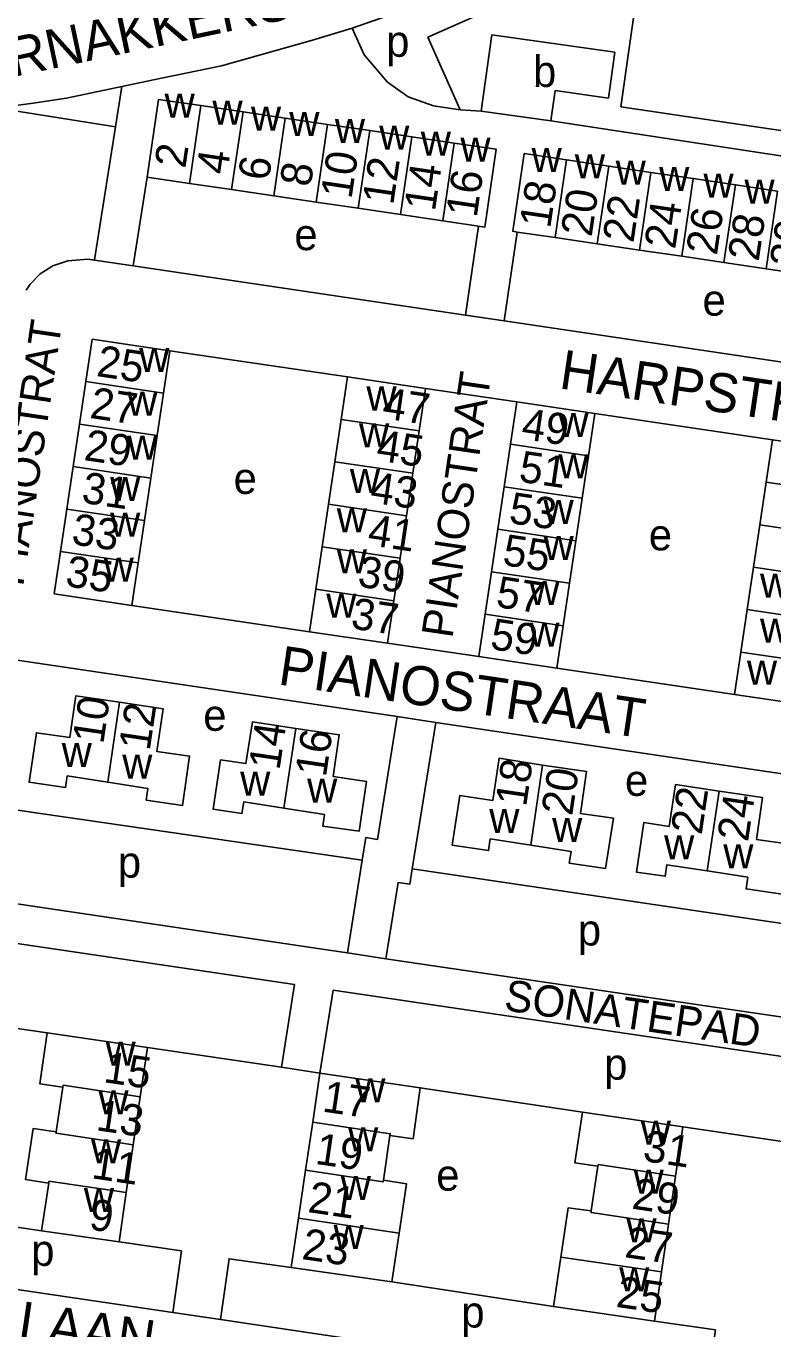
# Model space of a CAD drawing. Extents: x 163012 to 165277, y 382513 to 383987.
# Drawn here: x 164369.8 to 164465.3, y 383209.4 to 383376 of the extents above; entities that cross this region are included whole.
import ezdxf

# ---------------------------------------------------------------- set-up
doc = ezdxf.new("R2010")
doc.units = 0
for name, color, linetype in [('BLT_Basislijn', 7, 'Continuous'), ('BLT_Bebouwing', 7, 'Continuous'), ('BLT_Centroide', 7, 'Continuous'), ('BLT_Huisnummer', 7, 'Continuous'), ('BLT_Huisnummer_ tussenligend', 7, 'Continuous'), ('BLT_Onderverdeling_panden', 7, 'Continuous'), ('BLT_Straatnaam', 7, 'Continuous'), ('BLT_Straatnaam_verkleind', 7, 'Continuous')]:
    doc.layers.add(name, color=color, linetype=linetype)

msp = doc.modelspace()

# ---------------------------------------------------------------- linework, layer by layer
at = {"layer": 'BLT_Basislijn'}
for p, q in [((164411.47, 383375.78), (164406.39, 383374.22)), ((164382.02, 383368.3), (164381.21, 383363.14)), ((164427.97, 383365.17), (164425.29, 383365.33)), ((164381.21, 383363.14), (164378.53, 383346.15)), ((164526.66, 383350.3), (164436.89, 383363.9)), ((164385.25, 383356.71), (164383.47, 383345.37)), ((164427.66, 383350.46), (164426, 383339.06)), ((164432.61, 383349.7), (164430.95, 383338.32)), ((164383.47, 383345.37), (164426, 383339.06)), ((164426, 383339.06), (164430.95, 383338.32)), ((164430.95, 383338.32), (164483.68, 383330.5)), ((164388.16, 383334.51), (164410.89, 383331.17)), ((164432.56, 383327.98), (164420.85, 383329.69)), ((164442.52, 383326.5), (164465.26, 383323.12)), ((164383.31, 383301.95), (164406.03, 383298.58)), ((164427.71, 383295.39), (164416, 383297.12)), ((164366.6, 383295.22), (164417.23, 383287.72)), ((164460.4, 383290.54), (164437.68, 383293.93)), ((164417.23, 383287.72), (164417.23, 383287.72)), ((164417.23, 383287.72), (164422.18, 383286.98)), ((164419.17, 383268.26), (164422.18, 383286.98)), ((164422.18, 383286.98), (164472.78, 383279.48)), ((164412.77, 383269.34), (164363.74, 383276.47)), ((164410.87, 383257.52), (164412.77, 383269.34)), ((164470.22, 383260.71), (164419.17, 383268.26)), ((164325.48, 383265.08), (164404.1, 383253.46)), ((164361.96, 383264.74), (164408.23, 383257.91)), ((164408.23, 383257.91), (164410.87, 383257.52)), ((164410.87, 383257.52), (164415.81, 383256.75)), ((164415.81, 383256.75), (164468.61, 383248.99)), ((164402.42, 383242.87), (164404.1, 383253.46)), ((164407.36, 383242.13), (164409.04, 383252.73)), ((164409.04, 383252.73), (164472.58, 383243.35)), ((164362.81, 383248.7), (164372.46, 383247.27)), ((164385.3, 383245.41), (164402.42, 383242.87)), ((164402.42, 383242.87), (164407.36, 383242.13)), ((164420.2, 383240.23), (164440.94, 383237.14)), ((164453.78, 383235.26), (164470.9, 383232.72)), ((164359.13, 383223.8), (164371.75, 383221.94)), ((164388.55, 383211.49), (164351.55, 383216.97)), ((164437.25, 383212.28), (164416.57, 383215.41)), ((164394.65, 383210.59), (164388.55, 383211.49)), ((164456.85, 383201.38), (164394.65, 383210.59))]:
    msp.add_line(p, q, dxfattribs=at)
for points in [[(164425.29, 383365.33), (164421.18, 383374.61), (164475.67, 383398.71), (164485.85, 383406.54), (164494.23, 383396.59)], [(164454, 383394.51), (164453.92, 383394.21), (164422.89, 383379.8), (164411.47, 383375.78)], [(164425.29, 383365.33), (164421.9, 383365.84), (164418.67, 383366.97), (164416, 383368.88), (164413, 383372.37), (164411.47, 383375.78)], [(164387.08, 383369.36), (164394.75, 383370.96), (164406.39, 383374.22)], [(164337.22, 383362.36), (164358.98, 383364.61), (164370.66, 383366.16), (164374.93, 383366.82), (164382.02, 383368.3)], [(164382.02, 383368.3), (164387.08, 383369.36)], [(164364.88, 383343.03), (164368.06, 383365.25), (164381.21, 383363.14)], [(164369.75, 383342.26), (164370.27, 383343.02), (164371.54, 383344.35), (164373.18, 383345.37), (164375.11, 383346.02), (164377.66, 383346.23), (164383.47, 383345.37)], [(164412.77, 383269.34), (164413.24, 383272.25), (164414.71, 383272.01), (164417.23, 383287.72)], [(164415.81, 383256.75), (164417.38, 383266.52), (164418.85, 383266.28), (164419.17, 383268.26)], [(164381.65, 383220.52), (164389.63, 383219.38), (164388.55, 383211.49)], [(164403.67, 383217.25), (164395.74, 383218.38), (164394.65, 383210.59)], [(164450.16, 383210.41), (164457.97, 383209.28), (164456.85, 383201.38)]]:
    msp.add_lwpolyline(points, dxfattribs=at)
at = {"layer": 'BLT_Bebouwing'}
for p, q in [((164429.35, 383374.94), (164427.97, 383365.17)), ((164445.11, 383372.7), (164429.35, 383374.94)), ((164444.27, 383366.82), (164445.11, 383372.7)), ((164436.89, 383363.9), (164437.44, 383367.79)), ((164437.44, 383367.79), (164444.27, 383366.82)), ((164392.12, 383365.86), (164397.52, 383365.06)), ((164402.93, 383364.26), (164397.52, 383365.06)), ((164427.97, 383365.17), (164436.89, 383363.9)), ((164402.93, 383364.26), (164408.33, 383363.47)), ((164413.73, 383362.67), (164408.33, 383363.47)), ((164413.73, 383362.67), (164419.13, 383361.87)), ((164424.53, 383361.08), (164419.13, 383361.87)), ((164438.92, 383358.93), (164444.32, 383358.13)), ((164449.72, 383357.33), (164444.32, 383358.13)), ((164449.72, 383357.33), (164455.12, 383356.53)), ((164460.52, 383355.73), (164455.12, 383356.53)), ((164396.06, 383355.12), (164390.66, 383355.91)), ((164396.06, 383355.12), (164401.46, 383354.32)), ((164460.52, 383355.73), (164465.92, 383354.93)), ((164406.86, 383353.52), (164401.46, 383354.32)), ((164406.86, 383353.52), (164412.26, 383352.73)), ((164417.66, 383351.93), (164412.26, 383352.73)), ((164417.66, 383351.93), (164423.07, 383351.13)), ((164427.66, 383350.46), (164423.07, 383351.13)), ((164437.44, 383348.99), (164432.61, 383349.7)), ((164442.84, 383348.19), (164437.44, 383348.99)), ((164442.84, 383348.19), (164448.25, 383347.39)), ((164453.65, 383346.59), (164448.25, 383347.39)), ((164453.65, 383346.59), (164459.05, 383345.79)), ((164464.45, 383344.99), (164459.05, 383345.79)), ((164464.45, 383344.99), (164469.85, 383344.19)), ((164377.39, 383330.57), (164378.2, 383336)), ((164378.2, 383336), (164388.16, 383334.51)), ((164388.16, 383334.51), (164387.35, 383329.09)), ((164410.08, 383325.74), (164410.89, 383331.17)), ((164410.89, 383331.17), (164420.85, 383329.69)), ((164377.39, 383330.57), (164376.58, 383325.13)), ((164420.85, 383329.69), (164420.04, 383324.27)), ((164386.54, 383323.66), (164387.35, 383329.09)), ((164431.75, 383322.55), (164432.56, 383327.98)), ((164432.56, 383327.98), (164442.52, 383326.5)), ((164442.52, 383326.5), (164441.72, 383321.08)), ((164375.77, 383319.7), (164376.58, 383325.13)), ((164410.08, 383325.74), (164409.27, 383320.31)), ((164386.54, 383323.66), (164385.73, 383318.23)), ((164419.23, 383318.84), (164420.04, 383324.27)), ((164464.45, 383317.69), (164465.26, 383323.12)), ((164465.26, 383323.12), (164475.22, 383321.64)), ((164431.75, 383322.55), (164430.94, 383317.12)), ((164440.91, 383315.64), (164441.72, 383321.08)), ((164375.77, 383319.7), (164374.96, 383314.27)), ((164408.46, 383314.88), (164409.27, 383320.31)), ((164384.92, 383312.8), (164385.73, 383318.23)), ((164419.23, 383318.84), (164418.42, 383313.41)), ((164430.13, 383311.69), (164430.94, 383317.12)), ((164464.45, 383317.69), (164463.64, 383312.26)), ((164408.46, 383314.88), (164407.65, 383309.45)), ((164440.91, 383315.64), (164440.1, 383310.21)), ((164374.15, 383308.84), (164374.96, 383314.27)), ((164384.92, 383312.8), (164384.12, 383307.37)), ((164417.62, 383307.98), (164418.42, 383313.41)), ((164430.13, 383311.69), (164429.33, 383306.25)), ((164462.83, 383306.83), (164463.64, 383312.26)), ((164406.84, 383304.02), (164407.65, 383309.45)), ((164439.29, 383304.78), (164440.1, 383310.21)), ((164374.15, 383308.84), (164373.34, 383303.41)), ((164417.62, 383307.98), (164416.81, 383302.54)), ((164383.31, 383301.95), (164384.12, 383307.37)), ((164428.52, 383300.82), (164429.33, 383306.25)), ((164462.83, 383306.83), (164462.02, 383301.4)), ((164439.29, 383304.78), (164438.48, 383299.35)), ((164373.34, 383303.41), (164383.31, 383301.95)), ((164406.84, 383304.02), (164406.03, 383298.58)), ((164416, 383297.12), (164416.81, 383302.54)), ((164461.21, 383295.97), (164462.02, 383301.4)), ((164428.52, 383300.82), (164427.71, 383295.39)), ((164406.03, 383298.58), (164416, 383297.12)), ((164437.68, 383293.93), (164438.48, 383299.35)), ((164427.71, 383295.39), (164437.68, 383293.93)), ((164461.21, 383295.97), (164460.4, 383290.54)), ((164460.4, 383290.54), (164470.37, 383289.07)), ((164372.46, 383247.27), (164385.3, 383245.41)), ((164385.3, 383245.41), (164384.37, 383239.1)), ((164407.36, 383242.13), (164406.43, 383235.83)), ((164407.36, 383242.13), (164420.2, 383240.23)), ((164374.46, 383240.34), (164373.62, 383234.59)), ((164384.37, 383239.1), (164383.47, 383232.96)), ((164440.94, 383237.14), (164453.78, 383235.26)), ((164406.43, 383235.83), (164405.52, 383229.7)), ((164453.78, 383235.26), (164452.86, 383228.96)), ((164383.47, 383232.96), (164382.57, 383226.83)), ((164416.32, 383234.16), (164415.48, 383228.41)), ((164405.52, 383229.7), (164404.61, 383223.57)), ((164442.94, 383230.2), (164442.08, 383224.5)), ((164372.65, 383228.06), (164371.75, 383221.94)), ((164452.86, 383228.96), (164451.97, 383222.82)), ((164382.57, 383226.83), (164381.65, 383220.52)), ((164404.61, 383223.57), (164403.67, 383217.25)), ((164451.97, 383222.82), (164451.08, 383216.69)), ((164381.65, 383220.52), (164371.75, 383221.94)), ((164417.49, 383221.66), (164416.57, 383215.41)), ((164438.19, 383218.6), (164437.25, 383212.28)), ((164416.57, 383215.41), (164403.67, 383217.25)), ((164451.08, 383216.69), (164450.16, 383210.41)), ((164450.16, 383210.41), (164437.25, 383212.28))]:
    msp.add_line(p, q, dxfattribs=at)
for points in [[(164445.85, 383365.73), (164448.2, 383382.26), (164464.26, 383379.98), (164465.4, 383387.97), (164470.33, 383387.27), (164471.06, 383392.44), (164476.19, 383391.71), (164476.3, 383392.47), (164480.14, 383394.04), (164480.24, 383394.52), (164479.74, 383394.63), (164480.6, 383400.43), (164489.39, 383399.13), (164488.53, 383393.29), (164483.85, 383393.94), (164483.29, 383390.7), (164494.41, 383389.12), (164494.19, 383387.59), (164496.79, 383387.22), (164496.19, 383382.97), (164493.96, 383383.29)], [(164392.12, 383365.86), (164386.72, 383366.65), (164385.25, 383356.71)], [(164498.26, 383358.53), (164472.16, 383362.24), (164472.1, 383361.83), (164445.85, 383365.73)], [(164424.53, 383361.08), (164429.93, 383360.28)], [(164429.93, 383360.28), (164428.47, 383350.34), (164427.66, 383350.46)], [(164432.61, 383349.7), (164432.04, 383349.79), (164433.51, 383359.73)], [(164433.51, 383359.73), (164438.92, 383358.93)], [(164385.25, 383356.71), (164390.66, 383355.91)], [(164381.71, 383289.55), (164376.14, 383290.38), (164375.34, 383285.03), (164371.09, 383285.66), (164370.15, 383279.33), (164374.79, 383278.64), (164375.01, 383280.13), (164380.2, 383279.32)], [(164380.2, 383279.32), (164385.34, 383278.53), (164385.13, 383277.04), (164389.77, 383276.37), (164390.67, 383282.66), (164386.48, 383283.27), (164387.29, 383288.72), (164381.71, 383289.55)], [(164404.28, 383286.21), (164398.72, 383287.04), (164397.89, 383281.7), (164394.64, 383282.18), (164393.7, 383275.87), (164397.38, 383275.32), (164397.6, 383276.81), (164402.76, 383276.01)], [(164402.76, 383276.01), (164407.93, 383275.2), (164407.72, 383273.72), (164412.36, 383273.05), (164413.3, 383279.42), (164409.07, 383280.05), (164409.84, 383285.39), (164404.28, 383286.21)], [(164435.86, 383281.52), (164430.31, 383282.42), (164429.47, 383277), (164425.25, 383277.62), (164424.3, 383271.28), (164428.94, 383270.59), (164429.16, 383272.07), (164434.35, 383271.27)], [(164434.35, 383271.27), (164439.49, 383270.47), (164439.27, 383268.98), (164443.92, 383268.31), (164444.91, 383274.72), (164440.7, 383275.32), (164441.45, 383280.7), (164435.86, 383281.52)], [(164458.43, 383278.19), (164452.86, 383279.02), (164452.05, 383273.68), (164448.8, 383274.17), (164447.86, 383267.84), (164451.55, 383267.29), (164451.77, 383268.78), (164456.9, 383267.98)], [(164456.9, 383267.98), (164462.1, 383267.17), (164461.88, 383265.69), (164466.52, 383265.02), (164467.44, 383271.39), (164463.23, 383271.99), (164463.99, 383277.36), (164458.43, 383278.19)], [(164372.46, 383247.27), (164371.5, 383240.77), (164374.46, 383240.34)], [(164420.2, 383240.23), (164419.28, 383233.73), (164416.32, 383234.16)], [(164440.94, 383237.14), (164439.98, 383230.65), (164442.94, 383230.2)], [(164373.62, 383234.59), (164370.65, 383235.02), (164369.69, 383228.5), (164372.65, 383228.06)], [(164415.48, 383228.41), (164418.42, 383227.96), (164417.49, 383221.66)], [(164442.08, 383224.5), (164439.13, 383224.89), (164438.19, 383218.6)]]:
    msp.add_lwpolyline(points, dxfattribs=at)
at = {"layer": 'BLT_Onderverdeling_panden'}
for p, q in [((164390.66, 383355.91), (164392.12, 383365.86)), ((164397.52, 383365.06), (164396.06, 383355.12)), ((164401.46, 383354.32), (164402.93, 383364.26)), ((164408.33, 383363.47), (164406.86, 383353.52)), ((164412.26, 383352.73), (164413.73, 383362.67)), ((164419.13, 383361.87), (164417.66, 383351.93)), ((164423.07, 383351.13), (164424.53, 383361.08)), ((164437.44, 383348.99), (164438.92, 383358.93)), ((164444.32, 383358.13), (164442.84, 383348.19)), ((164448.25, 383347.39), (164449.72, 383357.33)), ((164455.12, 383356.53), (164453.65, 383346.59)), ((164459.05, 383345.79), (164460.52, 383355.73)), ((164465.92, 383354.93), (164464.45, 383344.99)), ((164387.35, 383329.09), (164377.39, 383330.57)), ((164376.58, 383325.13), (164386.54, 383323.66)), ((164420.04, 383324.27), (164410.08, 383325.74)), ((164441.72, 383321.08), (164431.75, 383322.55)), ((164385.73, 383318.23), (164375.77, 383319.7)), ((164409.27, 383320.31), (164419.23, 383318.84)), ((164430.94, 383317.12), (164440.91, 383315.64)), ((164474.41, 383316.22), (164464.45, 383317.69)), ((164418.42, 383313.41), (164408.46, 383314.88)), ((164374.96, 383314.27), (164384.92, 383312.8)), ((164440.1, 383310.21), (164430.13, 383311.69)), ((164463.64, 383312.26), (164473.6, 383310.79)), ((164407.65, 383309.45), (164417.62, 383307.98)), ((164384.12, 383307.37), (164374.15, 383308.84)), ((164429.33, 383306.25), (164439.29, 383304.78)), ((164472.79, 383305.36), (164462.83, 383306.83)), ((164416.81, 383302.54), (164406.84, 383304.02)), ((164462.02, 383301.4), (164471.99, 383299.93)), ((164438.48, 383299.35), (164428.52, 383300.82)), ((164471.18, 383294.49), (164461.21, 383295.97)), ((164381.71, 383289.55), (164380.2, 383279.32)), ((164404.28, 383286.21), (164402.76, 383276.01)), ((164435.86, 383281.52), (164434.35, 383271.27)), ((164458.43, 383278.19), (164456.9, 383267.98)), ((164417.49, 383221.66), (164404.61, 383223.57)), ((164451.08, 383216.69), (164438.19, 383218.6))]:
    msp.add_line(p, q, dxfattribs=at)
for points in [[(164384.37, 383239.1), (164374.49, 383240.56), (164374.46, 383240.34)], [(164383.47, 383232.96), (164373.59, 383234.42), (164373.62, 383234.59)], [(164416.32, 383234.16), (164416.35, 383234.36), (164406.43, 383235.83)], [(164415.48, 383228.41), (164415.46, 383228.23), (164405.52, 383229.7)], [(164452.86, 383228.96), (164442.98, 383230.42), (164442.94, 383230.2)], [(164382.57, 383226.83), (164372.68, 383228.29), (164372.65, 383228.06)], [(164451.97, 383222.82), (164442.05, 383224.29), (164442.08, 383224.5)]]:
    msp.add_lwpolyline(points, dxfattribs=at)

# ---------------------------------------------------------------- texts
at = {"layer": 'BLT_Centroide'}
for s, p in [('p', (164415.83, 383372.11)), ('b', (164434.63, 383368.25)), ('w', (164387.48, 383364.32)), ('w', (164393.6, 383363.41)), ('w', (164398.53, 383362.68)), ('w', (164403.43, 383361.96)), ('w', (164409.27, 383361.09)), ('w', (164414.94, 383360.25)), ('w', (164420.26, 383359.46)), ('w', (164425.33, 383358.71)), ('w', (164434.44, 383357.36)), ('w', (164439.97, 383356.55)), ('w', (164445.2, 383355.77)), ('w', (164450.76, 383354.95)), ('w', (164456.43, 383354.11)), ('w', (164461.68, 383353.33)), ('e', (164404.09, 383347.38)), ('e', (164456.32, 383339)), ('w', (164384.22, 383331.8)), ('w', (164413.31, 383326.87)), ('w', (164382.71, 383326.19)), ('w', (164437.87, 383323.49)), ('w', (164412.36, 383322.15)), ('w', (164382.71, 383320.59)), ('w', (164437.87, 383318.19)), ('w', (164380.51, 383315.29)), ('e', (164396.31, 383316.2)), ('w', (164411.19, 383316.31)), ('w', (164435.97, 383312.36)), ('w', (164380.51, 383310.74)), ('w', (164409.51, 383311.29)), ('e', (164449.44, 383308.98)), ('w', (164435.97, 383307.74)), ('w', (164379.68, 383304.99)), ('w', (164409.51, 383306.05)), ('w', (164434.16, 383301.98)), ('w', (164463.67, 383302.94)), ('w', (164408.17, 383300.38)), ('w', (164434.16, 383296.68)), ('w', (164463.67, 383297.18)), ('w', (164462, 383291.81)), ('e', (164392.43, 383285.9)), ('w', (164374.31, 383281.28)), ('w', (164382.06, 383279.8)), ('w', (164397.15, 383277.61)), ('w', (164405.72, 383276.72)), ('e', (164446.39, 383277.58)), ('w', (164429.02, 383272.83)), ('w', (164437.07, 383271.7)), ('w', (164451.4, 383269.45)), ('w', (164458.97, 383268.32)), ('p', (164381.5, 383267.12)), ('p', (164440.36, 383258.44)), ('w', (164379.93, 383243.09)), ('p', (164443.73, 383241.28)), ('w', (164411.88, 383238.38)), ('w', (164379.01, 383236.84)), ('w', (164410.96, 383232.12)), ('w', (164448.41, 383232.97)), ('w', (164378.07, 383230.59)), ('e', (164422.24, 383227.08)), ('w', (164447.49, 383226.72)), ('w', (164410.02, 383225.88)), ('w', (164377.15, 383224.34)), ('w', (164446.57, 383220.47)), ('w', (164409.1, 383219.62)), ('p', (164370.41, 383217.47)), ('w', (164445.65, 383214.22)), ('p', (164425.45, 383209.58))]:
    msp.add_text(s, height=4, dxfattribs=at).set_placement(p)
at = {"layer": 'BLT_Huisnummer'}
for s, rotation, p in [('2', 81.5821, (164390.13, 383357.75)), ('10', 81.5821, (164411.39, 383353.83)), ('6', 81.5821, (164400.81, 383356.15)), ('14', 81.5821, (164422.07, 383352.25)), ('18', 81.5821, (164436.82, 383350.07)), ('22', 81.5821, (164447.47, 383348.22)), ('26', 81.5821, (164458.15, 383346.62)), ('30', 81.5821, (164468.83, 383345.04)), ('25', 351.5821, (164378.65, 383331.29)), ('47', 351.5821, (164415.2, 383325.89)), ('49', 351.5821, (164433.01, 383323.25)), ('29', 351.5821, (164377.05, 383320.54)), ('53', 351.5821, (164431.42, 383312.5)), ('41', 351.5821, (164413.34, 383309.68)), ('35', 351.5821, (164374.66, 383304.42)), ('37', 351.5821, (164411.2, 383299.01)), ('59', 351.5821, (164429.02, 383296.37)), ('10', 81.5821, (164379.63, 383284.11)), ('12', 81.5821, (164385.57, 383283.25)), ('14', 81.5821, (164402.18, 383280.77)), ('16', 81.5821, (164408.12, 383279.89)), ('18', 81.5821, (164433.74, 383276.1)), ('20', 81.5821, (164439.63, 383274.94)), ('22', 81.5821, (164456.2, 383272.51)), ('24', 81.5821, (164462.13, 383271.61)), ('15', 351.581, (164379.55, 383240.98)), ('17', 351.581, (164407.55, 383237.22)), ('31', 351.581, (164448.57, 383230.9)), ('9', 351.581, (164377.68, 383222.15)), ('23', 351.581, (164404.93, 383218.35)), ('25', 351.581, (164445.14, 383212.24))]:
    msp.add_text(s, height=4, rotation=rotation, dxfattribs=at).set_placement(p)
at = {"layer": 'BLT_Huisnummer_ tussenligend'}
for s, rotation, p in [('4', 81.5821, (164395.47, 383356.94)), ('8', 81.5821, (164406.16, 383355.37)), ('12', 81.5821, (164416.73, 383353.06)), ('16', 81.5821, (164427.41, 383351.45)), ('20', 81.5821, (164442.12, 383348.99)), ('24', 81.5821, (164452.81, 383347.41)), ('28', 81.5821, (164463.49, 383345.84)), ('27', 351.5821, (164377.8, 383325.93)), ('45', 351.5821, (164414.45, 383320.5)), ('51', 351.5821, (164432.69, 383317.8)), ('31', 351.5821, (164376.74, 383315.1)), ('43', 351.5821, (164413.66, 383315.13)), ('33', 351.5821, (164375.46, 383309.79)), ('55', 351.5821, (164430.61, 383307.12)), ('39', 351.5821, (164412.06, 383304.38)), ('57', 351.5821, (164429.76, 383301.76)), ('13', 351.581, (164378.59, 383234.83)), ('19', 351.581, (164406.64, 383230.53)), ('11', 351.581, (164378.01, 383228.69)), ('21', 351.581, (164405.7, 383224.36)), ('29', 351.581, (164447.16, 383224.8)), ('27', 351.581, (164446.24, 383218.59))]:
    msp.add_text(s, height=4, rotation=rotation, dxfattribs=at).set_placement(p)
at = {"layer": 'BLT_Straatnaam'}
for s, rotation, p in [('DOORNAKKERSWEG', 11.924, (164353.16, 383366.36)), ('HARPSTRAAT', 351.5769, (164437.84, 383329.72)), ('PIANOSTRAAT', 351.5769, (164401.88, 383291.86)), ('KLAVECIMBELLAAN', 351.5769, (164322.62, 383214.82))]:
    msp.add_text(s, height=5, rotation=rotation, dxfattribs=at).set_placement(p)
at = {"layer": 'BLT_Straatnaam_verkleind'}
for s, rotation, p in [('PIANOSTRAT', 81.5928, (164369.38, 383304.28)), ('PIANOSTRAT', 81.5928, (164424.3, 383297.64)), ('SONATEPAD', 351.5928, (164430.79, 383250.18))]:
    msp.add_text(s, height=4, rotation=rotation, dxfattribs=at).set_placement(p)

doc.saveas('drawing.dxf')
